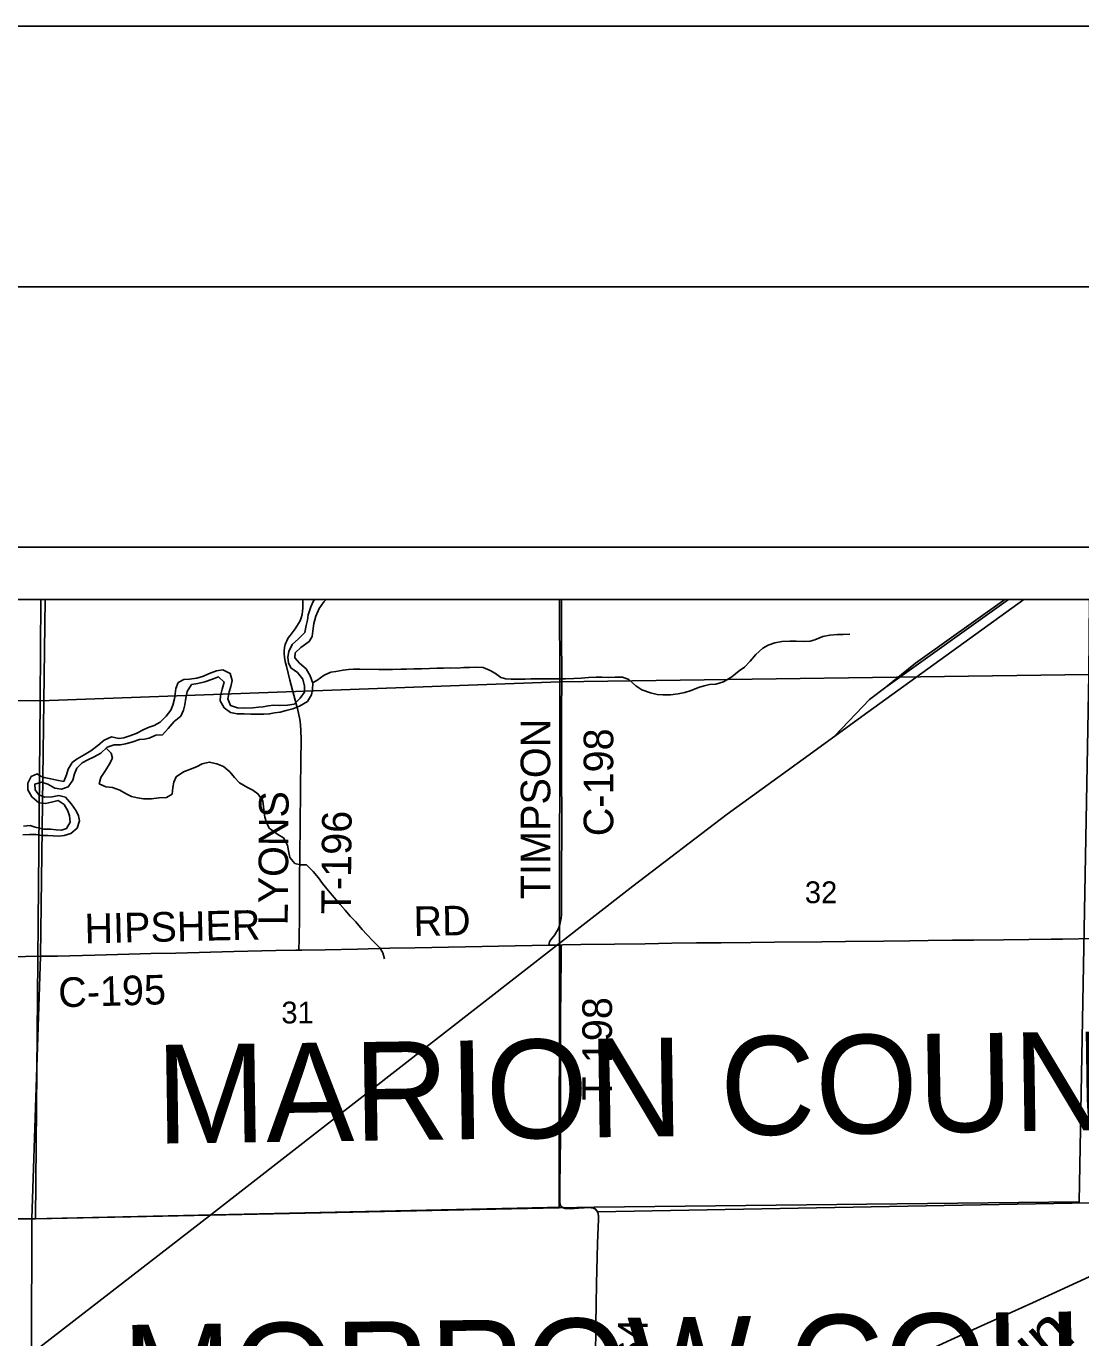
# Model space of a CAD drawing. Extents: x 0 to 45.9, y 0 to 22.
# Drawn here: x 5.466 to 7.492, y 19.483 to 22 of the extents above; entities that cross this region are included whole.
import ezdxf

# ---------------------------------------------------------------- set-up
doc = ezdxf.new("R2010")
doc.units = 0
for name, color, linetype in [('Default', 7, 'Continuous'), ('GM_X_County_Road', 7, 'Continuous'), ('GM_X_County_Road_Text', 7, 'Continuous'), ('GM_X_County_Text', 7, 'Continuous'), ('GM_X_Major_River', 7, 'Continuous'), ('GM_X_Minor_River', 7, 'Continuous'), ('GM_X_Minor_River_Text', 7, 'Continuous'), ('GM_X_Rail_Line', 7, 'Continuous'), ('GM_X_Section', 7, 'Continuous'), ('GM_X_Section_Text', 7, 'Continuous'), ('GM_X_State_Route', 7, 'Continuous'), ('GM_X_Township_Road', 7, 'Continuous'), ('GM_X_Township_Road_Text', 7, 'Continuous'), ('SH_Cut_Line', 7, 'Continuous'), ('SH_Data', 7, 'Continuous'), ('SH_Text', 7, 'Continuous')]:
    doc.layers.add(name, color=color, linetype=linetype)

msp = doc.modelspace()

# ---------------------------------------------------------------- linework, layer by layer
at = {"layer": 'Default'}
for points in [[(5.5025, 20.9), (2.1, 20.9), (2.1, 19.7114), (2.15, 19.7113), (3.7367, 19.7072), (5.0826, 19.712), (5.4773, 19.7108), (5.4937, 20.2154)], [(5.4943, 20.9), (4.477, 20.9), (4.4764, 20.7161), (5.4933, 20.7051)], [(6.4902, 20.9), (5.4943, 20.9), (5.4933, 20.7051), (6.4911, 20.7416)], [(7.5085, 20.9), (6.4902, 20.9), (6.4911, 20.7416), (7.5073, 20.7557)], [(2.1, 19.7114), (2.1, 14.1), (5.4538, 14.1), (5.4606, 15.6588), (5.4651, 16.7018), (5.4694, 17.7061), (5.4802, 18.3214), (5.4737, 18.7216), (5.4752, 19.0482), (5.4759, 19.2109), (5.4773, 19.7108), (5.0826, 19.712), (3.7367, 19.7072), (2.15, 19.7113)]]:
    msp.add_lwpolyline(points, close=True, dxfattribs=at)
for points in [[(8.9, 20.9), (5.5025, 20.9), (5.4937, 20.2154), (5.4773, 19.7108), (6.496, 19.7332), (6.4974, 19.7324), (6.4989, 19.7318), (6.5011, 19.7314), (6.5043, 19.731), (6.5104, 19.7308), (6.526, 19.7319), (6.5447, 19.733), (6.5508, 19.7327), (6.5539, 19.7323), (6.557, 19.7312), (6.5594, 19.7297), (6.5608, 19.7284), (6.5618, 19.7271), (6.5626, 19.7257), (6.5632, 19.7246), (7.5798, 19.7427)], [(7.5798, 19.7427), (6.5632, 19.7246), (6.5626, 19.7257), (6.5618, 19.7271), (6.5608, 19.7284), (6.5594, 19.7297), (6.557, 19.7312), (6.5539, 19.7323), (6.5508, 19.7327), (6.5447, 19.733), (6.526, 19.7319), (6.5104, 19.7308), (6.5043, 19.731), (6.5011, 19.7314), (6.4989, 19.7318), (6.4974, 19.7324), (6.496, 19.7332), (5.4773, 19.7108), (5.4759, 19.2109)]]:
    msp.add_lwpolyline(points, dxfattribs=at)
at = {"layer": 'GM_X_County_Road'}
for points in [[(6.4702, 20.2363), (6.4706, 20.2395), (6.4715, 20.2429), (6.4731, 20.2459), (6.4755, 20.249), (6.4814, 20.2563), (6.4849, 20.2615), (6.4879, 20.2671), (6.4891, 20.27), (6.4911, 20.2759), (6.4926, 20.2821), (6.4935, 20.2883), (6.494, 20.2945), (6.4943, 20.3144), (6.4946, 20.3884), (6.4947, 20.4466), (6.4948, 20.4901), (6.4945, 20.5521), (6.4945, 20.6639), (6.4944, 20.698), (6.4948, 20.7321), (6.4947, 20.7663), (6.4946, 20.8159), (6.4944, 20.9)], [(6.4937, 20.2365), (6.4967, 20.2366), (6.5312, 20.2374), (6.5961, 20.2383), (6.6551, 20.239), (6.7062, 20.2399), (6.7536, 20.2405), (6.8009, 20.2409), (6.8577, 20.2415), (6.9037, 20.2419), (6.9943, 20.2427), (7.0396, 20.2434), (7.1129, 20.2442), (7.1633, 20.2446), (7.1986, 20.245), (7.2454, 20.2456), (7.2858, 20.2461), (7.3432, 20.2467), (7.3918, 20.2473), (7.4349, 20.2478), (7.4567, 20.248), (7.5188, 20.2489)], [(5.4364, 20.214), (5.4929, 20.2148)], [(5.4929, 20.2148), (5.4939, 20.2148), (5.5266, 20.2153), (5.598, 20.2173), (5.685, 20.2195), (5.7055, 20.22), (5.7533, 20.2211), (5.8652, 20.2239), (5.9459, 20.2259), (5.984, 20.2268), (5.9899, 20.2269)], [(5.9899, 20.2269), (5.9955, 20.2269), (6.0401, 20.2275), (6.1022, 20.2288), (6.1643, 20.2302), (6.2126, 20.2314), (6.3102, 20.2331), (6.4056, 20.2347), (6.4377, 20.2356), (6.4702, 20.2363)], [(6.4702, 20.2363), (6.4773, 20.2364), (6.4937, 20.2365)]]:
    msp.add_lwpolyline(points, dxfattribs=at)
at = {"layer": 'GM_X_Major_River'}
for points in [[(5.574, 20.5859), (5.5847, 20.5917), (5.597, 20.5976), (5.6093, 20.6049), (5.622, 20.6164), (5.635, 20.6207), (5.6475, 20.6208), (5.657, 20.6225), (5.6688, 20.6257), (5.6836, 20.6307), (5.6931, 20.6316), (5.7026, 20.6337), (5.7152, 20.6392), (5.7281, 20.64), (5.7386, 20.6523), (5.7506, 20.6658), (5.763, 20.6758), (5.7681, 20.6874), (5.7706, 20.6973), (5.7728, 20.7105), (5.7753, 20.7234), (5.7839, 20.7365), (5.7957, 20.7385), (5.8094, 20.7416), (5.8224, 20.7463), (5.8357, 20.751), (5.8465, 20.7412), (5.8424, 20.7277), (5.8391, 20.7148), (5.8386, 20.7053), (5.8462, 20.6919), (5.8585, 20.6829), (5.8714, 20.6803), (5.885, 20.6804), (5.8975, 20.6798), (5.9228, 20.6793), (5.9338, 20.6802), (5.9433, 20.6819), (5.954, 20.6836), (5.9654, 20.6864), (5.978, 20.6899), (5.9913, 20.6949), (6.0063, 20.7041), (6.0141, 20.7169), (6.0162, 20.7271), (6.0165, 20.7388), (6.0119, 20.7534), (6.0038, 20.7668), (5.9912, 20.7774), (5.9823, 20.7878), (5.9829, 20.7973), (5.9937, 20.8077), (6.0095, 20.8188), (6.0153, 20.8285), (6.0176, 20.844), (6.0185, 20.8535), (6.0226, 20.8679), (6.029, 20.8822), (6.038, 20.8953), (6.0422, 20.9)], [(6.0198, 20.9), (6.0171, 20.8961), (6.0131, 20.8859), (6.0079, 20.8704), (6.0062, 20.8602), (6.0041, 20.85), (6.0011, 20.8364), (5.9891, 20.8245), (5.9768, 20.8134), (5.9708, 20.7998), (5.9687, 20.7888), (5.97, 20.7782), (5.9747, 20.7686), (5.987, 20.7596), (5.9973, 20.7465), (6.0005, 20.7331), (6.0006, 20.7217), (5.9924, 20.7105), (5.9808, 20.6986), (5.9679, 20.6966), (5.9523, 20.6965), (5.9421, 20.6971), (5.9311, 20.6958), (5.9216, 20.6937), (5.9121, 20.6928), (5.9015, 20.6919), (5.8864, 20.6914), (5.872, 20.6917), (5.8588, 20.6962), (5.8534, 20.7088), (5.856, 20.7224), (5.8592, 20.733), (5.8617, 20.744), (5.8582, 20.7577), (5.844, 20.7648), (5.8314, 20.7625), (5.8165, 20.7567), (5.8066, 20.7523), (5.7937, 20.7488), (5.78, 20.7468), (5.769, 20.7459), (5.7579, 20.7401), (5.7539, 20.7291), (5.7521, 20.7189), (5.7508, 20.7091), (5.7479, 20.697), (5.7443, 20.6872), (5.7353, 20.6756), (5.7237, 20.664), (5.7122, 20.6578), (5.7027, 20.6546), (5.6924, 20.6499), (5.6771, 20.6426), (5.6652, 20.6379)], [(5.6652, 20.6379), (5.6538, 20.6344), (5.6443, 20.633), (5.63, 20.6364), (5.6158, 20.6298), (5.6039, 20.6195), (5.5904, 20.6095), (5.5778, 20.6014), (5.564, 20.5941), (5.5543, 20.5867), (5.5465, 20.5739), (5.5436, 20.5634), (5.5384, 20.5506), (5.5252, 20.5527), (5.5135, 20.5553), (5.5004, 20.5582), (5.4934, 20.5604)], [(5.4598, 20.4478), (5.4723, 20.4486), (5.4852, 20.4487), (5.4957, 20.447), (5.5078, 20.4464), (5.5181, 20.4458), (5.529, 20.4455), (5.5393, 20.4465), (5.5522, 20.4504), (5.5642, 20.4611), (5.5686, 20.4747), (5.5666, 20.4843), (5.5619, 20.4939), (5.553, 20.5066), (5.5416, 20.5205), (5.5288, 20.5234), (5.5159, 20.521), (5.5022, 20.5205), (5.4902, 20.525), (5.4832, 20.5346), (5.483, 20.5453), (5.4956, 20.5488), (5.508, 20.5455), (5.5211, 20.5376), (5.534, 20.5358), (5.5469, 20.5401), (5.5559, 20.5529), (5.5588, 20.5653), (5.5632, 20.5759), (5.574, 20.5859)], [(5.4934, 20.5604), (5.4872, 20.5649), (5.4758, 20.5598), (5.4695, 20.5471), (5.4696, 20.5341), (5.4768, 20.5207), (5.4906, 20.5094), (5.5031, 20.5084), (5.5145, 20.5108), (5.5278, 20.5136), (5.539, 20.5061), (5.5463, 20.4938), (5.5495, 20.4842), (5.5508, 20.4724), (5.5437, 20.4604), (5.5342, 20.4572), (5.524, 20.4578), (5.513, 20.4588), (5.4998, 20.4587), (5.4836, 20.4628), (5.4738, 20.4657), (5.4613, 20.4648)]]:
    msp.add_lwpolyline(points, dxfattribs=at)
at = {"layer": 'GM_X_Minor_River'}
for points in [[(6.0161, 20.74), (6.0242, 20.744), (6.0384, 20.7547), (6.0514, 20.7601), (6.0609, 20.7618), (6.0749, 20.7642), (6.0852, 20.7651), (6.0947, 20.7657), (6.1068, 20.7658), (6.1435, 20.7651), (6.1564, 20.7652), (6.17, 20.7653), (6.1859, 20.7661), (6.1969, 20.7662), (6.2109, 20.7663), (6.2253, 20.7668), (6.2409, 20.7672), (6.2549, 20.7677), (6.2674, 20.7678), (6.2806, 20.7683), (6.2943, 20.768), (6.3068, 20.7693), (6.3178, 20.7694), (6.331, 20.7695), (6.3439, 20.7692), (6.3574, 20.7637), (6.3675, 20.7574), (6.3776, 20.7499), (6.3874, 20.7475), (6.3976, 20.7465), (6.4112, 20.7466), (6.4245, 20.7467), (6.4351, 20.7472), (6.4457, 20.7474), (6.4627, 20.7474), (6.4733, 20.7476), (6.4843, 20.7473), (6.5021, 20.7477), (6.518, 20.7482), (6.5324, 20.7486), (6.5464, 20.7498), (6.5608, 20.7507), (6.5718, 20.7504), (6.5839, 20.7502), (6.5976, 20.7507), (6.6112, 20.7508), (6.6236, 20.746), (6.637, 20.7339), (6.6486, 20.7264), (6.6651, 20.7208), (6.6783, 20.7175), (6.6889, 20.7169), (6.7036, 20.7169), (6.7181, 20.7185), (6.731, 20.7209), (6.7432, 20.7252), (6.7573, 20.731), (6.768, 20.7338), (6.7787, 20.7363), (6.7908, 20.7372), (6.8053, 20.7414), (6.8214, 20.751), (6.8356, 20.7628), (6.8456, 20.7698), (6.8565, 20.7814), (6.8677, 20.794), (6.8808, 20.8063), (6.8912, 20.8118), (6.9042, 20.8164), (6.9178, 20.8192), (6.9326, 20.82), (6.9451, 20.8194), (6.9595, 20.8191), (6.9716, 20.82), (6.9811, 20.8221), (6.996, 20.8286), (7.0097, 20.8313), (7.0245, 20.8322), (7.0351, 20.8323), (7.048, 20.8332)], [(5.62, 20.6146), (5.6297, 20.6049), (5.6318, 20.5949), (5.6255, 20.5829), (5.6188, 20.5713), (5.6098, 20.5578), (5.6065, 20.5461), (5.6189, 20.5398), (5.6317, 20.5387), (5.646, 20.5335), (5.6583, 20.5264), (5.6685, 20.5216), (5.6798, 20.5191), (5.6915, 20.517), (5.707, 20.5174), (5.7207, 20.5187), (5.7358, 20.5199), (5.7466, 20.5261), (5.748, 20.539), (5.7497, 20.5488), (5.7541, 20.5594), (5.7683, 20.5686), (5.782, 20.574), (5.7931, 20.5787), (5.8042, 20.5841), (5.8179, 20.5876), (5.8326, 20.5843), (5.845, 20.5791), (5.8573, 20.5686), (5.8665, 20.5581), (5.8758, 20.5481), (5.8915, 20.5386), (5.9012, 20.5335), (5.9113, 20.5268), (5.9205, 20.513), (5.9221, 20.5019), (5.9234, 20.4913), (5.9247, 20.4817), (5.9279, 20.4714), (5.933, 20.4607), (5.9498, 20.4489), (5.9602, 20.4423), (5.9683, 20.4284), (5.9699, 20.4174), (5.9727, 20.4048), (5.9823, 20.3932), (5.9928, 20.3903), (6.0046, 20.3901), (6.0176, 20.3773), (6.0275, 20.3653), (6.0353, 20.3549), (6.0471, 20.3406), (6.0578, 20.3274), (6.0689, 20.3143), (6.0785, 20.3034), (6.0885, 20.2922), (6.0992, 20.281), (6.1114, 20.2663), (6.1203, 20.2566), (6.1329, 20.2442), (6.1451, 20.2314), (6.151, 20.2214), (6.1545, 20.2103)]]:
    msp.add_lwpolyline(points, dxfattribs=at)
at = {"layer": 'GM_X_Rail_Line'}
for p, q in [((7.1173, 20.7312), (7.3528, 20.9)), ((5.4785, 19.4538), (5.8183, 19.7169))]:
    msp.add_line(p, q, dxfattribs=at)
for points in [[(5.8183, 19.7169), (6.6316, 20.3492), (6.8125, 20.4876), (6.9772, 20.6069), (7.0711, 20.6749), (7.3824, 20.9)], [(7.1173, 20.7312), (7.174, 20.7776), (7.3456, 20.9)], [(7.0189, 20.6371), (7.0593, 20.6805), (7.0859, 20.7077), (7.1173, 20.7312)]]:
    msp.add_lwpolyline(points, dxfattribs=at)
at = {"layer": 'GM_X_Section'}
for points in [[(6.4911, 20.7416), (7.5073, 20.7557), (7.4888, 19.7433), (6.557, 19.7334), (6.4896, 19.732)], [(5.4933, 20.7051), (6.4911, 20.7416), (6.4896, 19.732), (5.4839, 19.711)], [(4.4764, 20.7161), (5.4933, 20.7051), (5.4839, 19.711), (4.4734, 19.7064)]]:
    msp.add_lwpolyline(points, close=True, dxfattribs=at)
at = {"layer": 'GM_X_State_Route'}
for points in [[(7.4519, 19.5741), (7.4839, 19.5886), (7.5789, 19.632)], [(6.8649, 19.3074), (6.8896, 19.3186), (6.9406, 19.3416), (7.0029, 19.3699), (7.0452, 19.3894), (7.1047, 19.4162), (7.1755, 19.4482), (7.2349, 19.4754), (7.3, 19.505), (7.399, 19.55), (7.4519, 19.5741)]]:
    msp.add_lwpolyline(points, dxfattribs=at)
at = {"layer": 'GM_X_Township_Road'}
msp.add_line((6.538, 19.7321), (6.5272, 19.7314), dxfattribs=at)
for points in [[(5.9854, 20.6967), (5.98, 20.7162), (5.9726, 20.7451), (5.966, 20.7718), (5.9639, 20.7805), (5.9621, 20.7889), (5.9614, 20.7951), (5.9614, 20.7988), (5.9616, 20.8014), (5.9622, 20.8078), (5.9634, 20.8131), (5.9647, 20.8167), (5.9665, 20.8203), (5.9695, 20.8258), (5.973, 20.8309), (5.9827, 20.8431), (5.9863, 20.8482), (5.9895, 20.8535), (5.9922, 20.859), (5.9944, 20.8648), (5.996, 20.8708), (5.997, 20.877), (5.9975, 20.8832), (5.9976, 20.8932), (5.9975, 20.9)], [(5.9899, 20.2269), (5.99, 20.2326), (5.9903, 20.2423), (5.991, 20.2965), (5.9913, 20.3586), (5.9919, 20.4145), (5.9924, 20.4607), (5.9926, 20.4863), (5.9929, 20.5144), (5.9932, 20.5391), (5.9937, 20.5885), (5.994, 20.6315), (5.9937, 20.6475), (5.9928, 20.6599), (5.9917, 20.6691), (5.9894, 20.6814), (5.9881, 20.687), (5.9865, 20.6928), (5.9854, 20.6967)], [(6.4962, 19.7326), (6.4949, 19.7341), (6.4933, 19.7359), (6.492, 19.7386), (6.4913, 19.7431), (6.4908, 19.7519), (6.4913, 19.773), (6.4916, 19.8209), (6.4921, 19.8664), (6.4923, 19.9255), (6.4927, 19.9877), (6.4922, 20.0653), (6.4923, 20.0995), (6.4928, 20.1534), (6.4936, 20.2112), (6.4936, 20.2269), (6.4937, 20.2365)], [(6.5272, 19.7314), (6.5262, 19.7313), (6.5107, 19.7303), (6.5045, 19.7305), (6.5013, 19.7308), (6.4992, 19.7313), (6.4976, 19.7319), (6.4962, 19.7326)], [(6.5634, 19.724), (6.5629, 19.7252), (6.5621, 19.7266), (6.561, 19.7279), (6.5597, 19.7292), (6.5572, 19.7307), (6.5541, 19.7318), (6.551, 19.7322), (6.5449, 19.7325), (6.538, 19.7321)], [(6.5563, 19.2235), (6.5564, 19.2318), (6.5569, 19.2753), (6.5572, 19.3094), (6.5581, 19.3654), (6.5593, 19.443), (6.5605, 19.5082), (6.5618, 19.5859), (6.5633, 19.6636), (6.5655, 19.7101), (6.5652, 19.7172), (6.5649, 19.7189), (6.5645, 19.721), (6.564, 19.7226), (6.5634, 19.724)]]:
    msp.add_lwpolyline(points, dxfattribs=at)
at = {"layer": 'SH_Cut_Line'}
for p, q in [((2, 21), (9, 21)), ((2.1, 20.9), (8.9, 20.9))]:
    msp.add_line(p, q, dxfattribs=at)
at = {"layer": 'SH_Data'}
msp.add_lwpolyline([(1.5, 21.5), (33.5, 21.5), (33.5, 0.5), (1.5, 0.5)], close=True, dxfattribs=at)
at = {"layer": 'SH_Text'}
msp.add_lwpolyline([(0, 0), (34, 0), (34, 22), (0, 22)], close=True, dxfattribs=at)
for points in [[(8.9, 20.9), (2.1, 20.9)], [(5.4759, 19.2109), (5.4773, 19.7108), (6.496, 19.7332), (6.4974, 19.7324), (6.4989, 19.7318), (6.5011, 19.7314), (6.5043, 19.731), (6.5104, 19.7308), (6.526, 19.7319), (6.5447, 19.733), (6.5508, 19.7327), (6.5539, 19.7323), (6.557, 19.7312), (6.5594, 19.7297), (6.5608, 19.7284), (6.5618, 19.7271), (6.5626, 19.7257), (6.5632, 19.7246), (7.5798, 19.7427)], [(7.5798, 19.7427), (6.5632, 19.7246), (6.5626, 19.7257), (6.5618, 19.7271), (6.5608, 19.7284), (6.5594, 19.7297), (6.557, 19.7312), (6.5539, 19.7323), (6.5508, 19.7327), (6.5447, 19.733), (6.526, 19.7319), (6.5104, 19.7308), (6.5043, 19.731), (6.5011, 19.7314), (6.4989, 19.7318), (6.4974, 19.7324), (6.496, 19.7332), (5.4773, 19.7108), (5.4759, 19.2109)]]:
    msp.add_lwpolyline(points, dxfattribs=at)

# ---------------------------------------------------------------- texts
at = {"layer": 'GM_X_County_Road_Text'}
for s, rotation, p in [('TIMPSON', 90, (6.4727, 20.3246)), ('C-198', 90.0011, (6.5937, 20.4453)), ('HIPSHER', 1.2838, (5.5788, 20.2396)), ('RD', 0.9872, (6.2105, 20.2537)), ('C-195', 1.6641, (5.5285, 20.1169))]:
    msp.add_text(s, height=0.05682, rotation=rotation, dxfattribs=at).set_placement(p)
at = {"layer": 'GM_X_County_Text'}
for s, rotation, p in [('MARION COUNTY', 0.8268, (5.7168, 19.8552)), ('MORROW COUNTY', 0.8203, (5.6522, 19.3177))]:
    msp.add_text(s, height=0.189394, rotation=rotation, dxfattribs=at).set_placement(p)
at = {"layer": 'GM_X_Minor_River_Text'}
msp.add_text('Run', height=0.09472, rotation=40.3114, dxfattribs=at).set_placement((7.3085, 19.3288))
at = {"layer": 'GM_X_Section_Text'}
for s, p in [('32', (6.9617, 20.3168)), ('31', (5.9563, 20.086))]:
    msp.add_text(s, height=0.04186, rotation=0, dxfattribs=at).set_placement(p)
at = {"layer": 'GM_X_Township_Road_Text'}
for s, rotation, p in [('LYONS', 89.5904, (5.9685, 20.2741)), ('T-196', 89.4403, (6.0895, 20.2954)), ('T-198', 90, (6.5912, 19.938)), ('T-64', 88.9333, (6.6571, 19.363))]:
    msp.add_text(s, height=0.05682, rotation=rotation, dxfattribs=at).set_placement(p)

doc.saveas('drawing.dxf')
